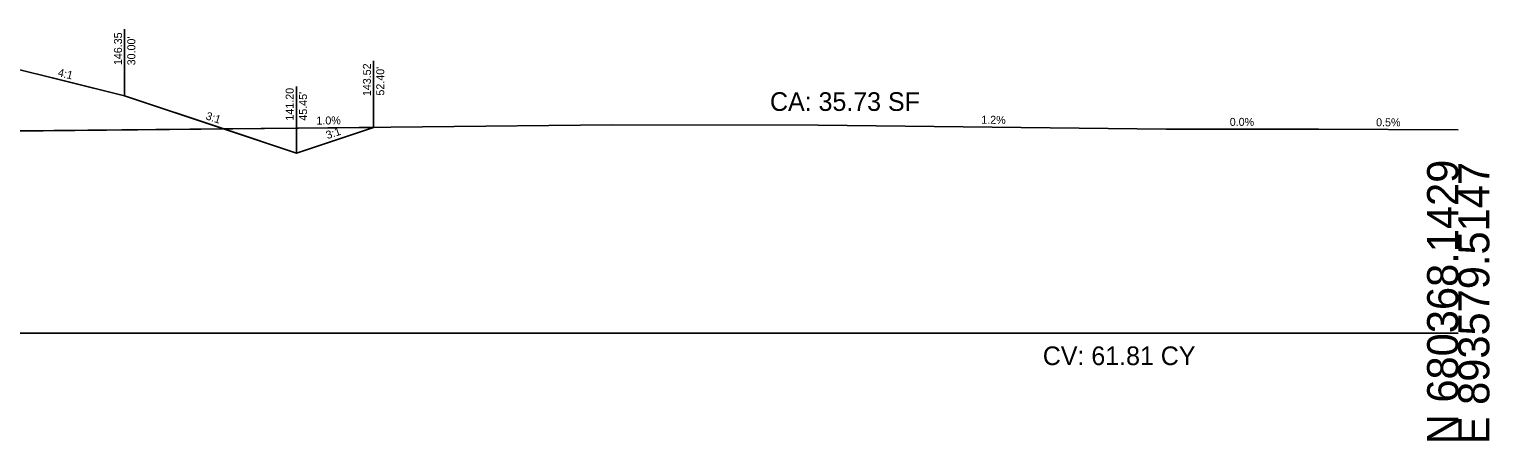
# Model space of a CAD drawing. Extents: x -26 to 4303, y -13 to 10775.
# Drawn here: x 171.4 to 302.8, y 9490.3 to 9527.4 of the extents above; entities that cross this region are included whole.
import ezdxf

# ---------------------------------------------------------------- set-up
doc = ezdxf.new("R2010")
doc.units = 0
for name, color, linetype in [('CONST_DCH', 7, 'Continuous'), ('CONST_LV3', 7, 'Continuous'), ('DTM_CORRIDOR', 7, 'Continuous'), ('DTM_X_GROUND', 7, 'Continuous'), ('SLOPE_STAKES_FILL', 7, 'Continuous'), ('XS_CELL', 7, 'Continuous'), ('XS_M_SHAPES_EARTHWORK', 7, 'Continuous'), ('XS_P_GROUND', 7, 'Continuous'), ('XS_P_TX_CLEARZONE', 7, 'Continuous'), ('XS_P_TX_FS_BS', 7, 'Continuous'), ('XS_SHEET_EW_TX_AREA', 7, 'Continuous'), ('XS_SHEET_EW_TX_VOLUME', 7, 'Continuous')]:
    doc.layers.add(name, color=color, linetype=linetype)

msp = doc.modelspace()

# ---------------------------------------------------------------- linework, layer by layer
at = {"layer": 'CONST_LV3'}
msp.add_lwpolyline([(180, 9521.35), (180, 9521.35), (173.51, 9522.98)], dxfattribs=at)
at = {"layer": 'DTM_X_GROUND'}
msp.add_lwpolyline([(150.04, 9518.02), (172.67, 9518.21), (223.87, 9518.75), (242.4, 9518.73), (273.71, 9518.35), (287.43, 9518.35), (300, 9518.29)], dxfattribs=at)
at = {"layer": 'XS_CELL'}
msp.add_line((150, 9500), (300, 9500), dxfattribs=at)
at = {"layer": 'XS_P_GROUND'}
for points in [[(195.45, 9516.2), (180, 9521.35), (180, 9521.35), (180, 9521.35), (169.24, 9524.04)], [(195.45, 9516.2), (202.4, 9518.52)]]:
    msp.add_lwpolyline(points, dxfattribs=at)
at = {"layer": 'XS_P_TX_CLEARZONE'}
for p, q in [((180, 9521.35), (180, 9527.35)), ((180, 9521.35), (180, 9527.35)), ((202.4, 9518.52), (202.4, 9524.52)), ((202.4, 9518.52), (202.4, 9524.52)), ((202.4, 9518.52), (202.4, 9524.52)), ((195.45, 9516.2), (195.45, 9522.2)), ((195.45, 9516.2), (195.45, 9522.2)), ((195.45, 9516.2), (195.45, 9522.2))]:
    msp.add_line(p, q, dxfattribs=at)
at = {"layer": 'XS_SHEET_EW_TX_AREA'}
for points in [[(188.92, 9518.38), (161.36, 9518.11), (147.25, 9517.96), (124.17, 9517.51), (112.12, 9517.27), (120, 9519.91), (130.76, 9522.6), (136, 9522.81), (136, 9522.37), (134, 9522.33), (134, 9521.61), (150, 9522.37), (165, 9523.09), (166, 9523.14), (166, 9523.67), (164, 9523.71), (164, 9524.15), (169.24, 9524.04), (180, 9521.35)], [(188.92, 9518.38), (202.4, 9518.52), (195.45, 9516.2)]]:
    msp.add_lwpolyline(points, close=True, dxfattribs=at)

# ---------------------------------------------------------------- texts
at = {"layer": 'CONST_DCH'}
msp.add_text('X', height=0.12, dxfattribs=at).set_placement((195.41, 9516.15))
at = {"layer": 'DTM_CORRIDOR'}
msp.add_text('X', height=0.12, dxfattribs=at).set_placement((202.36, 9518.46))
at = {"layer": 'SLOPE_STAKES_FILL'}
msp.add_text('X', height=0.12, dxfattribs=at).set_placement((179.96, 9521.29))
at = {"layer": 'XS_CELL'}
for s, p in [('N 680368.1429', (300, 9490)), ('E 893579.5147', (302.8, 9490))]:
    msp.add_text(s, height=2.8, rotation=90, dxfattribs=at).set_placement(p)
at = {"layer": 'XS_M_SHAPES_EARTHWORK'}
msp.add_text('CV: 61.81 CY', height=1.68, dxfattribs=at).set_placement((262.62, 9497.12))
at = {"layer": 'XS_P_TX_CLEARZONE'}
for s, p in [('146.35', (179.76, 9524.12)), ('146.35', (179.76, 9524.12)), ("30.00'", (180.96, 9524.1)), ("30.00'", (180.96, 9524.1)), ('143.52', (202.16, 9521.33)), ('143.52', (202.16, 9521.33)), ('143.52', (202.16, 9521.33)), ("52.40'", (203.36, 9521.38)), ("52.40'", (203.36, 9521.38)), ("52.40'", (203.36, 9521.38)), ('141.20', (195.21, 9519.13)), ('141.20', (195.21, 9519.13)), ('141.20', (195.21, 9519.13)), ("45.45'", (196.41, 9519.12)), ("45.45'", (196.41, 9519.12)), ("45.45'", (196.41, 9519.12))]:
    msp.add_text(s, height=0.72, rotation=90, dxfattribs=at).set_placement(p)
at = {"layer": 'XS_P_TX_FS_BS'}
for s, rotation, p in [('4:1', 346.3161, (173.94, 9523.14)), ('3:1', 341.5668, (187.24, 9519.26)), ('1.0%', 0.596, (197.26, 9518.77)), ('1.2%', 359.3162, (257.08, 9518.85)), ('0.0%', 359.9849, (279.44, 9518.65)), ('0.5%', 359.732, (292.61, 9518.62)), ('3:1', 18.4349, (198.25, 9517.45))]:
    msp.add_text(s, height=0.72, rotation=rotation, dxfattribs=at).set_placement(p)
at = {"layer": 'XS_SHEET_EW_TX_VOLUME'}
msp.add_text('CA: 35.73 SF', height=1.68, dxfattribs=at).set_placement((238.07, 9520))

doc.saveas('drawing.dxf')
